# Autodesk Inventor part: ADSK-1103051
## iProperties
Shininess: 41.0
Length Units: 11272
Angle Units: 11279
Time Units: 11290
Mass Units: 11286
Length Display Precision: 4
Angle Display Precision: 2
Compacted: True
Created: 2000-08
Part Number: ADSK-1103051
Document SubType Name: Modeling
Mass: 3.87512 g
Surface Area: 71.1553 cm^2
Volume: 3.87512 cm^3
Density: 1 g/cm^3
Density: 0.0
Volumn: 0.0
Area: 0.0
PropertySet Name: Model Information
Control State: 0
Master: False
Checked Out: False
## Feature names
1. Fillet2
2. Fillet4
3. Fillet5
4. Hole1
5. Hole2
